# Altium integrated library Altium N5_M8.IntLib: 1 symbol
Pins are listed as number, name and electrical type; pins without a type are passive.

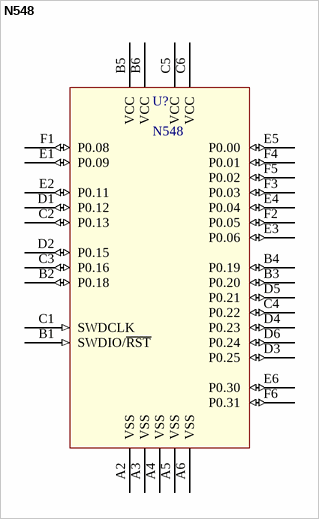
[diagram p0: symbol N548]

## N548
designator U?
N548 Module
footprint N548
pins: A2 VSS (power), A3 VSS (power), A4 VSS (power), A5 VSS (power), A6 VSS (power), B1 SWDIO/~{RST} (in), B2 P0.18 (io), B3 P0.20 (io), B4 P0.19 (io), B5 VCC (power), B6 VCC (power), C1 SWDCLK (in), C2 P0.13 (io), C3 P0.16 (io), C4 P0.22 (io), C5 VCC (power), C6 VCC (power), D1 P0.12 (io), D2 P0.15 (io), D3 P0.25 (io), D4 P0.23 (io), D5 P0.21 (io), D6 P0.24 (io), E1 P0.09 (io), E2 P0.11 (io), E3 P0.06 (io), E4 P0.04 (io), E5 P0.00 (io), E6 P0.30 (io), F1 P0.08 (io), F2 P0.05 (io), F3 P0.03 (io), F4 P0.01 (io), F5 P0.02 (io), F6 P0.31 (io)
